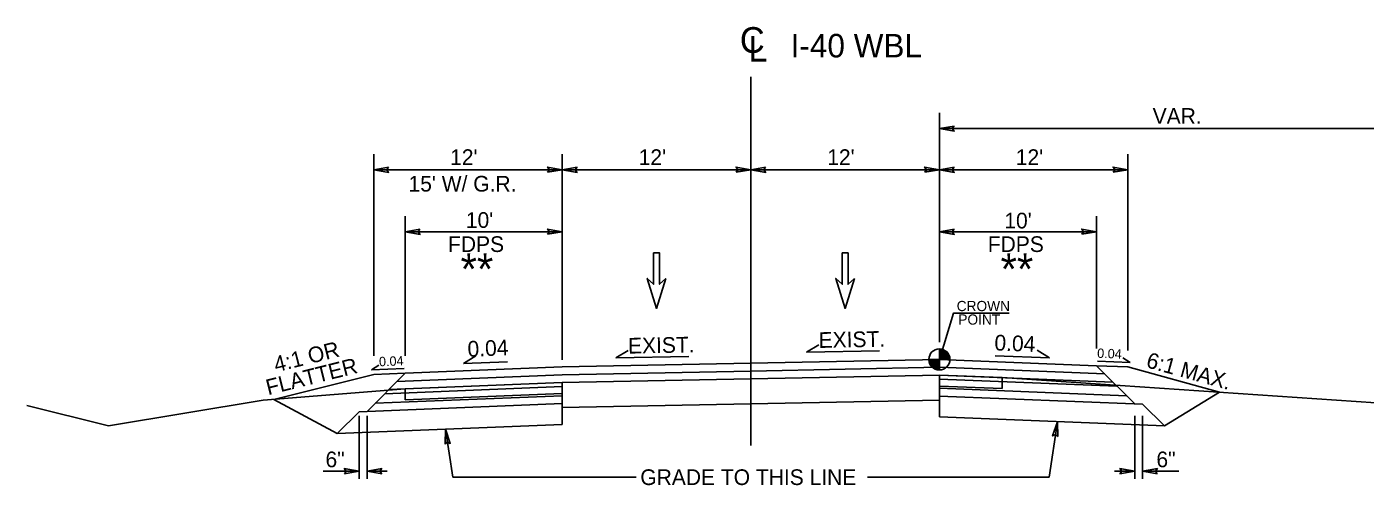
# Model space of a CAD drawing. Extents: x 1553195 to 1553792, y 810516 to 810787.
# Drawn here: x 1553195.3 to 1553280.5, y 810700.2 to 810729.4 of the extents above; entities that cross this region are included whole.
import ezdxf

# ---------------------------------------------------------------- set-up
doc = ezdxf.new("R2010")
doc.units = 0
for name, color, linetype in [('Old_Level_11', 7, 'Continuous'), ('Prop Dimension', 7, 'Continuous'), ('Prop DSN Text', 7, 'Continuous'), ('Prop Pavement Schedule Description CELL', 7, 'Continuous'), ('Prop Shade Light', 7, 'Continuous'), ('Prop Typical Section', 7, 'Continuous'), ('Sheet Sticker Incomplete CELL', 7, 'Continuous'), ('Typical Grade Point Symbol CELL', 7, 'Continuous'), ('Typical Pavement Slope CELL', 7, 'Continuous'), ('Typical Text ID Circle CELL', 7, 'Continuous'), ('z - Construction', 7, 'Continuous')]:
    doc.layers.add(name, color=color, linetype=linetype)

msp = doc.modelspace()

# ---------------------------------------------------------------- linework, layer by layer
at = {"layer": 'Old_Level_11'}
for p, q in [((1553253.391, 810708.172), (1553253.391, 810708.843)), ((1553252.72, 810708.172), (1553253.391, 810708.172)), ((1553253.389, 810707.501), (1553253.391, 810708.172)), ((1553253.391, 810708.172), (1553253.389, 810707.501)), ((1553254.062, 810708.172), (1553253.391, 810708.172))]:
    msp.add_line(p, q, dxfattribs=at)
for points in [[(1553253.397, 810708.843), (1553253.397, 810708.843), (1553253.397, 810708.172)], [(1553253.41, 810708.843), (1553253.41, 810708.172)], [(1553253.424, 810708.842), (1553253.424, 810708.172)], [(1553253.437, 810708.842), (1553253.437, 810708.172)], [(1553253.451, 810708.84), (1553253.451, 810708.172)], [(1553253.464, 810708.839), (1553253.464, 810708.172)], [(1553253.477, 810708.837), (1553253.477, 810708.172)], [(1553253.491, 810708.836), (1553253.491, 810708.172)], [(1553253.504, 810708.834), (1553253.504, 810708.172)], [(1553253.518, 810708.832), (1553253.518, 810708.172)], [(1553253.531, 810708.828), (1553253.531, 810708.172)], [(1553253.545, 810708.825), (1553253.545, 810708.172)], [(1553253.558, 810708.823), (1553253.558, 810708.172)], [(1553253.571, 810708.818), (1553253.571, 810708.172)], [(1553253.585, 810708.815), (1553253.585, 810708.172)], [(1553253.598, 810708.811), (1553253.598, 810708.172)], [(1553253.612, 810708.806), (1553253.612, 810708.172)], [(1553253.625, 810708.802), (1553253.625, 810708.172)], [(1553253.639, 810708.796), (1553253.639, 810708.172)], [(1553253.652, 810708.79), (1553253.652, 810708.172)], [(1553253.665, 810708.784), (1553253.665, 810708.172)], [(1553253.679, 810708.778), (1553253.679, 810708.172)], [(1553253.692, 810708.772), (1553253.692, 810708.172)], [(1553253.706, 810708.764), (1553253.706, 810708.172)], [(1553253.719, 810708.757), (1553253.719, 810708.172)], [(1553253.733, 810708.749), (1553253.733, 810708.172)], [(1553253.746, 810708.742), (1553253.746, 810708.172)], [(1553253.759, 810708.733), (1553253.759, 810708.172)], [(1553253.773, 810708.724), (1553253.773, 810708.172)], [(1553253.786, 810708.714), (1553253.786, 810708.172)], [(1553253.8, 810708.705), (1553253.8, 810708.172)], [(1553253.813, 810708.694), (1553253.813, 810708.172)], [(1553253.827, 810708.682), (1553253.827, 810708.172)], [(1553253.84, 810708.67), (1553253.84, 810708.172)], [(1553253.853, 810708.658), (1553253.853, 810708.172)], [(1553253.867, 810708.645), (1553253.867, 810708.172)], [(1553253.88, 810708.632), (1553253.88, 810708.172)], [(1553253.894, 810708.617), (1553253.894, 810708.172)], [(1553252.723, 810708.172), (1553252.723, 810708.099)], [(1553252.736, 810708.172), (1553252.736, 810708.02)], [(1553252.749, 810708.172), (1553252.749, 810707.972)], [(1553252.763, 810708.172), (1553252.763, 810707.932)], [(1553252.776, 810708.172), (1553252.776, 810707.9)], [(1553252.79, 810708.172), (1553252.79, 810707.872)], [(1553252.803, 810708.172), (1553252.803, 810707.847)], [(1553252.817, 810708.172), (1553252.817, 810707.823)], [(1553252.83, 810708.172), (1553252.83, 810707.802)], [(1553252.843, 810708.172), (1553252.843, 810707.783)], [(1553252.857, 810708.172), (1553252.857, 810707.765)], [(1553252.87, 810708.172), (1553252.87, 810707.748)], [(1553252.884, 810708.172), (1553252.884, 810707.732)], [(1553252.897, 810708.172), (1553252.897, 810707.717)], [(1553252.911, 810708.172), (1553252.911, 810707.702)], [(1553252.924, 810708.172), (1553252.924, 810707.689)], [(1553252.937, 810708.172), (1553252.937, 810707.677)], [(1553252.951, 810708.172), (1553252.951, 810707.665)], [(1553252.964, 810708.172), (1553252.964, 810707.653)], [(1553252.978, 810708.172), (1553252.978, 810707.642)], [(1553252.991, 810708.172), (1553252.991, 810707.632)], [(1553253.005, 810708.172), (1553253.005, 810707.623)], [(1553253.018, 810708.172), (1553253.018, 810707.614)], [(1553253.031, 810708.172), (1553253.031, 810707.605)], [(1553253.045, 810708.172), (1553253.045, 810707.596)], [(1553253.058, 810708.172), (1553253.058, 810707.589)], [(1553253.072, 810708.172), (1553253.072, 810707.581)], [(1553253.085, 810708.172), (1553253.085, 810707.574)], [(1553253.099, 810708.172), (1553253.099, 810707.568)], [(1553253.112, 810708.172), (1553253.112, 810707.562)], [(1553253.125, 810708.172), (1553253.125, 810707.556)], [(1553253.139, 810708.172), (1553253.139, 810707.55)], [(1553253.152, 810708.172), (1553253.152, 810707.544)], [(1553253.166, 810708.172), (1553253.166, 810707.539)], [(1553253.179, 810708.172), (1553253.179, 810707.535)], [(1553253.193, 810708.172), (1553253.193, 810707.53)], [(1553253.206, 810708.172), (1553253.206, 810707.527)], [(1553253.219, 810708.172), (1553253.219, 810707.523)], [(1553253.233, 810708.172), (1553253.233, 810707.52)], [(1553253.246, 810708.172), (1553253.246, 810707.517)], [(1553253.26, 810708.172), (1553253.26, 810707.514)], [(1553253.273, 810708.172), (1553253.273, 810707.511)], [(1553253.286, 810708.172), (1553253.286, 810707.51)], [(1553253.3, 810708.172), (1553253.3, 810707.507)], [(1553253.313, 810708.172), (1553253.313, 810707.505)], [(1553253.327, 810708.172), (1553253.327, 810707.504)], [(1553253.34, 810708.172), (1553253.34, 810707.502)], [(1553253.354, 810708.172), (1553253.354, 810707.502)], [(1553253.367, 810708.172), (1553253.367, 810707.501)], [(1553253.381, 810708.172), (1553253.381, 810707.501), (1553253.381, 810707.501)], [(1553253.907, 810708.6), (1553253.907, 810708.172)], [(1553253.921, 810708.584), (1553253.921, 810708.172)], [(1553253.934, 810708.566), (1553253.934, 810708.172)], [(1553253.947, 810708.546), (1553253.947, 810708.172)], [(1553253.961, 810708.526), (1553253.961, 810708.172)], [(1553253.974, 810708.503), (1553253.974, 810708.172)], [(1553253.988, 810708.479), (1553253.988, 810708.172)], [(1553254.001, 810708.451), (1553254.001, 810708.172)], [(1553254.015, 810708.42), (1553254.015, 810708.172)], [(1553254.028, 810708.382), (1553254.028, 810708.172)], [(1553254.041, 810708.336), (1553254.041, 810708.172)], [(1553254.055, 810708.268), (1553254.055, 810708.172)]]:
    msp.add_lwpolyline(points, dxfattribs=at)
msp.add_circle((1553253.39, 810708.172), 0.671, dxfattribs=at)
for start, end in [(359.99048, 89.99048), (179.99048, 269.99048)]:
    msp.add_arc((1553253.39, 810708.172), 0.671, start, end, dxfattribs=at)
at = {"layer": 'Prop Dimension'}
for p, q in [((1553232.792, 810708.275), (1553233.575, 810708.748)), ((1553244.924, 810708.636), (1553245.707, 810709.109)), ((1553244.924, 810708.636), (1553249.584, 810708.729)), ((1553260.39, 810708.268), (1553259.617, 810708.757)), ((1553217.251, 810707.507), (1553217.715, 810707.8)), ((1553223.109, 810707.91), (1553223.883, 810708.399)), ((1553223.109, 810707.91), (1553225.904, 810708.022)), ((1553232.792, 810708.275), (1553237.453, 810708.368)), ((1553260.39, 810708.268), (1553256.94, 810708.406)), ((1553265.529, 810707.987), (1553263.459, 810708.07)), ((1553265.529, 810707.987), (1553265.065, 810708.28)), ((1553217.251, 810707.507), (1553219.321, 810707.59))]:
    msp.add_line(p, q, dxfattribs=at)
at = {"layer": 'Prop DSN Text'}
for points in [[(1553254.328, 810723.046), (1553253.39, 810722.884), (1553254.333, 810722.718), (1553254.213, 810722.884)], [(1553218.328, 810720.421), (1553217.39, 810720.259), (1553218.333, 810720.093), (1553218.213, 810720.259)], [(1553228.453, 810720.098), (1553229.39, 810720.259), (1553228.448, 810720.426), (1553228.567, 810720.259)], [(1553230.328, 810720.421), (1553229.39, 810720.259), (1553230.333, 810720.093), (1553230.213, 810720.259)], [(1553240.453, 810720.098), (1553241.39, 810720.259), (1553240.448, 810720.426), (1553240.567, 810720.259)], [(1553242.328, 810720.421), (1553241.39, 810720.259), (1553242.333, 810720.093), (1553242.213, 810720.259)], [(1553252.453, 810720.098), (1553253.39, 810720.259), (1553252.448, 810720.426), (1553252.567, 810720.259)], [(1553254.328, 810720.421), (1553253.39, 810720.259), (1553254.333, 810720.093), (1553254.213, 810720.259)], [(1553264.453, 810720.098), (1553265.39, 810720.259), (1553264.448, 810720.426), (1553264.567, 810720.259)], [(1553220.328, 810716.469), (1553219.39, 810716.307), (1553220.333, 810716.141), (1553220.213, 810716.307)], [(1553228.453, 810716.146), (1553229.39, 810716.307), (1553228.448, 810716.474), (1553228.567, 810716.307)], [(1553254.328, 810716.469), (1553253.39, 810716.307), (1553254.333, 810716.141), (1553254.213, 810716.307)], [(1553262.453, 810716.146), (1553263.39, 810716.307), (1553262.448, 810716.474), (1553262.567, 810716.307)], [(1553221.93, 810702.777), (1553221.949, 810703.728), (1553222.255, 810702.821), (1553222.072, 810702.914)], [(1553260.923, 810703.254), (1553260.904, 810704.205), (1553260.598, 810703.298), (1553260.78, 810703.392)], [(1553215.522, 810700.892), (1553216.46, 810701.054), (1553215.517, 810701.221), (1553215.637, 810701.054)], [(1553217.897, 810700.892), (1553216.96, 810701.054), (1553217.902, 810701.221), (1553217.782, 810701.054)], [(1553264.883, 810700.892), (1553265.821, 810701.054), (1553264.878, 810701.221), (1553264.998, 810701.054)], [(1553267.258, 810700.892), (1553266.321, 810701.054), (1553267.263, 810701.221), (1553267.144, 810701.054)]]:
    msp.add_lwpolyline(points, close=True, dxfattribs=at)
at = {"layer": 'Prop Pavement Schedule Description CELL'}
for p, q in [((1553217.39, 810708.399), (1553217.39, 810721.259)), ((1553219.39, 810708.407), (1553219.39, 810717.307)), ((1553222.413, 810700.669), (1553221.949, 810703.728)), ((1553260.367, 810700.669), (1553260.904, 810704.205)), ((1553234.088, 810700.669), (1553222.413, 810700.669)), ((1553260.367, 810700.669), (1553248.81, 810700.669))]:
    msp.add_line(p, q, dxfattribs=at)
at = {"layer": 'Prop Typical Section'}
msp.add_line((1553241.39, 810702.686), (1553241.39, 810726.173), dxfattribs=at)
for points in [[(1553235.984, 810713.333), (1553235.578, 810712.958), (1553235.578, 810714.959), (1553235.203, 810714.959), (1553235.203, 810712.958), (1553234.797, 810713.333), (1553235.39, 810711.427)], [(1553235.984, 810713.333), (1553235.578, 810712.958), (1553235.578, 810714.959), (1553235.203, 810714.959), (1553235.203, 810712.958), (1553234.797, 810713.333), (1553235.39, 810711.427)], [(1553247.984, 810713.333), (1553247.578, 810712.958), (1553247.578, 810714.959), (1553247.203, 810714.959), (1553247.203, 810712.958), (1553246.797, 810713.333), (1553247.39, 810711.427)], [(1553247.984, 810713.333), (1553247.578, 810712.958), (1553247.578, 810714.959), (1553247.203, 810714.959), (1553247.203, 810712.958), (1553246.797, 810713.333), (1553247.39, 810711.427)]]:
    msp.add_lwpolyline(points, close=True, dxfattribs=at)
at = {"layer": 'Sheet Sticker Incomplete CELL'}
for p, q in [((1553263.39, 810707.772), (1553265.39, 810707.692)), ((1553217.39, 810707.212), (1553211.037, 810705.624)), ((1553219.39, 810707.292), (1553217.39, 810707.212)), ((1553265.39, 810707.692), (1553271.227, 810706.077)), ((1553271.227, 810706.077), (1553267.71, 810703.933)), ((1553215.071, 810703.453), (1553211.037, 810705.624))]:
    msp.add_line(p, q, dxfattribs=at)
at = {"layer": 'Typical Grade Point Symbol CELL'}
for p, q in [((1553241.39, 810706.932), (1553229.39, 810706.692)), ((1553253.39, 810707.172), (1553241.39, 810706.932)), ((1553253.39, 810707.172), (1553257.39, 810707.012)), ((1553253.39, 810707.172), (1553253.39, 810705.587)), ((1553257.39, 810707.012), (1553257.39, 810706.313)), ((1553257.39, 810707.012), (1553283.39, 810705.255)), ((1553219.39, 810706.292), (1553210.344, 810705.569)), ((1553229.39, 810706.692), (1553219.39, 810706.292)), ((1553219.39, 810706.292), (1553219.39, 810705.593)), ((1553229.39, 810706.692), (1553229.39, 810705.107)), ((1553253.39, 810706.473), (1553257.39, 810706.313)), ((1553195.306, 810705.233), (1553200.517, 810703.931)), ((1553210.344, 810705.569), (1553200.517, 810703.931)), ((1553229.39, 810705.993), (1553219.39, 810705.593)), ((1553241.39, 810705.347), (1553229.39, 810705.107)), ((1553253.39, 810705.587), (1553241.39, 810705.347))]:
    msp.add_line(p, q, dxfattribs=at)
at = {"layer": 'Typical Pavement Slope CELL'}
for p, q in [((1553253.39, 810708.172), (1553229.39, 810707.692)), ((1553253.39, 810708.172), (1553263.39, 810707.772)), ((1553263.39, 810707.772), (1553265.821, 810705.342)), ((1553219.39, 810707.292), (1553216.96, 810704.862)), ((1553229.39, 810707.192), (1553218.869, 810706.771)), ((1553229.39, 810707.692), (1553219.39, 810707.292)), ((1553241.39, 810707.432), (1553229.39, 810707.192)), ((1553253.39, 810707.672), (1553241.39, 810707.432)), ((1553253.39, 810707.672), (1553263.911, 810707.251)), ((1553253.39, 810707.172), (1553264.432, 810706.731)), ((1553253.39, 810706.922), (1553264.692, 810706.47)), ((1553229.39, 810706.442), (1553218.088, 810705.99)), ((1553229.39, 810706.692), (1553218.349, 810706.251)), ((1553253.39, 810706.339), (1553265.3, 810705.862)), ((1553229.39, 810705.359), (1553216.46, 810704.842)), ((1553229.39, 810705.859), (1553217.48, 810705.382)), ((1553253.39, 810705.839), (1553266.321, 810705.322)), ((1553253.39, 810705.587), (1553253.39, 810704.506)), ((1553266.321, 810705.322), (1553267.71, 810703.933)), ((1553216.46, 810704.842), (1553215.071, 810703.453)), ((1553229.39, 810705.107), (1553229.39, 810704.026)), ((1553253.39, 810704.506), (1553267.71, 810703.933)), ((1553229.39, 810704.026), (1553215.071, 810703.453))]:
    msp.add_line(p, q, dxfattribs=at)
at = {"layer": 'Typical Text ID Circle CELL'}
msp.add_lwpolyline([(1553253.39, 810708.172), (1553254.294, 810711.126), (1553257.832, 810711.126)], dxfattribs=at)
at = {"layer": 'z - Construction'}
for p, q in [((1553253.39, 810709.282), (1553253.39, 810723.884)), ((1553283.39, 810722.884), (1553253.39, 810722.884)), ((1553229.39, 810708.137), (1553229.39, 810721.259)), ((1553265.39, 810708.744), (1553265.39, 810721.259)), ((1553229.39, 810720.259), (1553217.39, 810720.259)), ((1553241.39, 810720.259), (1553229.39, 810720.259)), ((1553253.39, 810720.259), (1553241.39, 810720.259)), ((1553265.39, 810720.259), (1553253.39, 810720.259)), ((1553263.39, 810708.861), (1553263.39, 810717.307)), ((1553229.39, 810716.307), (1553219.39, 810716.307)), ((1553263.39, 810716.307), (1553253.39, 810716.307)), ((1553216.46, 810700.566), (1553216.46, 810704.579)), ((1553216.96, 810700.566), (1553216.96, 810704.579)), ((1553265.821, 810700.566), (1553265.821, 810704.579)), ((1553266.321, 810700.566), (1553266.321, 810704.579)), ((1553216.46, 810701.054), (1553214.162, 810701.054)), ((1553218.248, 810701.054), (1553216.96, 810701.054)), ((1553264.532, 810701.054), (1553265.821, 810701.054)), ((1553266.321, 810701.054), (1553268.618, 810701.054))]:
    msp.add_line(p, q, dxfattribs=at)

# ---------------------------------------------------------------- texts
at = {"layer": 'Prop Pavement Schedule Description CELL'}
for s, height, p in [('I-40 WBL', 1.5, (1553243.921, 810727.415)), ('VAR.', 1, (1553266.963, 810723.185)), ("12'", 1, (1553222.252, 810720.56)), ("12'", 1, (1553234.252, 810720.56)), ("12'", 1, (1553246.252, 810720.56)), ("12'", 1, (1553258.252, 810720.56)), ("15' W/ G.R.", 1, (1553219.603, 810718.868)), ("10'", 1, (1553223.252, 810716.555)), ("10'", 1, (1553257.522, 810716.519)), ('FDPS', 1, (1553222.118, 810715.018)), ('FDPS', 1, (1553256.47, 810715.018)), ('**', 2, (1553222.915, 810712.933)), ('**', 2, (1553257.283, 810712.933)), ('6"', 1, (1553214.318, 810701.302)), ('6"', 1, (1553267.202, 810701.302)), ('GRADE TO THIS LINE', 1, (1553234.355, 810700.169))]:
    msp.add_text(s, height=height, dxfattribs=at).set_placement(p)
for s, height, rotation, p in [('EXIST.', 1, 1.14587, (1553233.581, 810708.541)), ('EXIST.', 1, 1.14587, (1553245.712, 810708.903)), ('0.04', 1, 357.70939, (1553256.878, 810708.751)), ('4:1 OR', 1, 14.03624, (1553211.172, 810707.345)), ('0.04', 1, 2.29061, (1553223.378, 810708.338)), ('0.04', 0.6, 357.70939, (1553263.422, 810708.277)), ('FLATTER', 1, 14.03624, (1553210.67, 810705.886)), ('0.04', 0.6, 2.29061, (1553217.735, 810707.732)), ('6:1 MAX.', 1, 344.53233, (1553266.491, 810707.688))]:
    msp.add_text(s, height=height, rotation=rotation, dxfattribs=at).set_placement(p)
at = {"layer": 'Prop Shade Light'}
msp.add_text('C', height=1.64, dxfattribs=at).set_placement((1553240.688, 810727.706))
msp.add_text('L', height=1.641, rotation=359.9469, dxfattribs=at).set_placement((1553241.233, 810727.146))
at = {"layer": 'Typical Text ID Circle CELL'}
for s, p in [('CROWN', (1553254.491, 810711.248)), ('POINT', (1553254.594, 810710.39))]:
    msp.add_text(s, height=0.6525, dxfattribs=at).set_placement(p)

doc.saveas('drawing.dxf')
